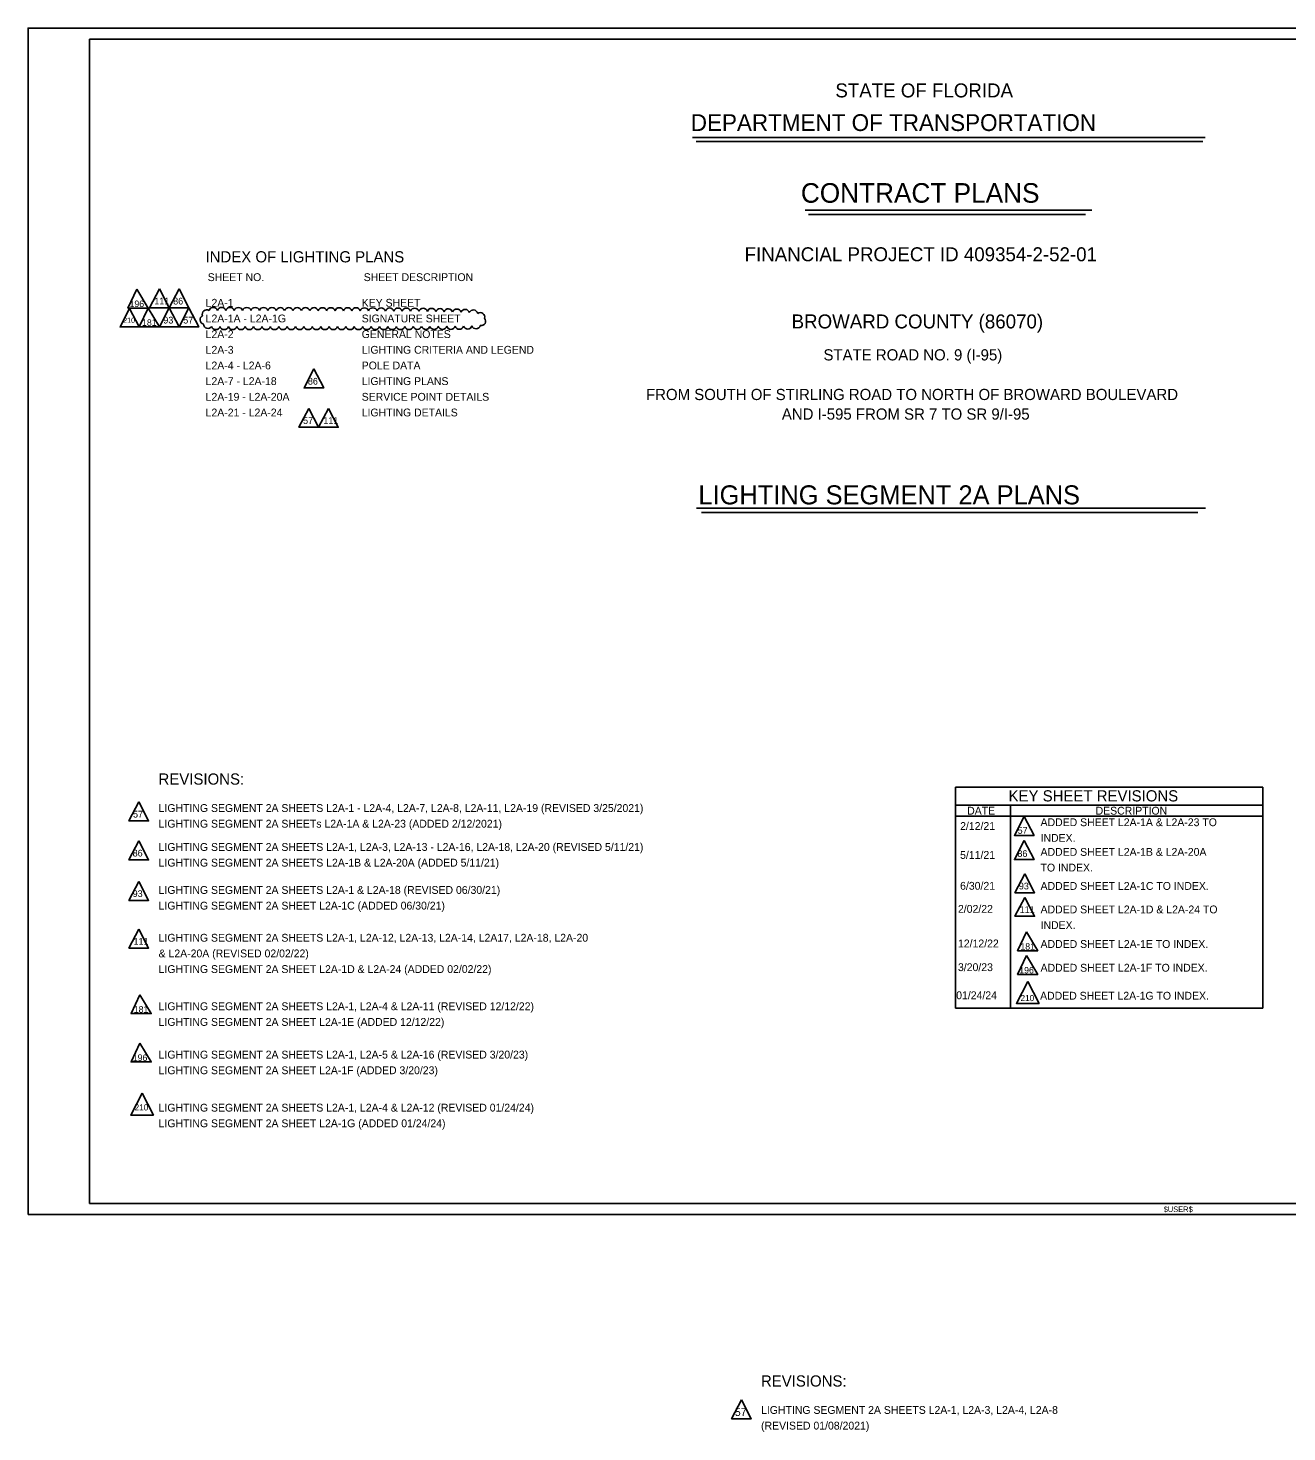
# Model space of a CAD drawing. Extents: x -820.2 to -798.7, y -2201.1 to -2188.5.
# Drawn here: x -820.23 to -808.98, y -2201.07 to -2188.52 of the extents above; entities that cross this region are included whole.
import ezdxf

# ---------------------------------------------------------------- set-up
doc = ezdxf.new("R2010")
doc.units = 0
for name, color, linetype in [('AdhocPoint_dp', 7, 'Continuous'), ('Cloud_dp', 7, 'Continuous'), ('PlotBorder_dp', 7, 'Continuous'), ('SheetBorder_dp', 7, 'Continuous'), ('SumBoxLines_dp', 7, 'Continuous'), ('TextLabel', 7, 'Continuous'), ('TextMinor', 7, 'Continuous'), ('TextNotes', 7, 'Continuous'), ('TextTitle', 7, 'Continuous')]:
    doc.layers.add(name, color=color, linetype=linetype)

msp = doc.modelspace()

# ---------------------------------------------------------------- linework, layer by layer
at = {"layer": 'AdhocPoint_dp'}
msp.add_line((-820.227, -2199.124), (-820.227, -2199.124), dxfattribs=at)
at = {"layer": 'Cloud_dp'}
for points in [[(-819.256, -2190.857), (-819.335, -2191.025), (-819.155, -2191.025)], [(-819.053, -2190.854), (-819.141, -2191.023), (-818.965, -2191.023)], [(-818.877, -2190.854), (-818.965, -2191.023), (-818.789, -2191.023)], [(-819.319, -2191.028), (-819.405, -2191.193), (-819.234, -2191.193)], [(-819.155, -2191.025), (-819.234, -2191.193), (-819.053, -2191.193)], [(-818.965, -2191.023), (-819.053, -2191.193), (-818.877, -2191.193)], [(-818.789, -2191.023), (-818.877, -2191.193), (-818.701, -2191.193)], [(-817.672, -2191.569), (-817.76, -2191.739), (-817.584, -2191.739)], [(-817.718, -2191.921), (-817.806, -2192.09), (-817.63, -2192.09)], [(-817.542, -2191.921), (-817.63, -2192.09), (-817.454, -2192.09)], [(-819.238, -2195.437), (-819.326, -2195.607), (-819.15, -2195.607)], [(-811.324, -2195.567), (-811.412, -2195.736), (-811.236, -2195.736)], [(-819.238, -2195.786), (-819.326, -2195.955), (-819.15, -2195.955)], [(-811.324, -2195.783), (-811.412, -2195.953), (-811.236, -2195.953)], [(-811.319, -2196.08), (-811.407, -2196.249), (-811.231, -2196.249)], [(-819.238, -2196.147), (-819.326, -2196.317), (-819.15, -2196.317)], [(-811.319, -2196.29), (-811.407, -2196.459), (-811.231, -2196.459)], [(-819.238, -2196.574), (-819.326, -2196.743), (-819.15, -2196.743)], [(-811.305, -2196.599), (-811.384, -2196.767), (-811.203, -2196.767)], [(-811.305, -2196.811), (-811.384, -2196.979), (-811.203, -2196.979)], [(-811.293, -2197.042), (-811.394, -2197.237), (-811.191, -2197.237)], [(-819.228, -2197.161), (-819.307, -2197.329), (-819.126, -2197.329)], [(-819.228, -2197.593), (-819.307, -2197.761), (-819.126, -2197.761)], [(-819.207, -2198.04), (-819.309, -2198.235), (-819.106, -2198.235)], [(-813.851, -2200.779), (-813.939, -2200.949), (-813.763, -2200.949)]]:
    msp.add_lwpolyline(points, close=True, dxfattribs=at)
for centre, radius, start, end in [((-818.631, -2191.079), 0.0393, 57.4429, 202.4429), ((-818.572, -2191.058), 0.0393, 17.4254, 162.4254), ((-818.497, -2191.058), 0.0393, 17.3487, 162.3487), ((-818.422, -2191.058), 0.0393, 17.3487, 162.3487), ((-818.347, -2191.059), 0.0393, 17.3487, 162.3487), ((-818.272, -2191.059), 0.0393, 17.3487, 162.3487), ((-818.197, -2191.059), 0.0393, 17.3487, 162.3487), ((-818.122, -2191.059), 0.0393, 17.3487, 162.3487), ((-818.047, -2191.059), 0.0393, 17.3487, 162.3487), ((-817.972, -2191.06), 0.0393, 17.3487, 162.3487), ((-817.897, -2191.06), 0.0393, 17.3487, 162.3487), ((-817.822, -2191.06), 0.0393, 17.3487, 162.3487), ((-817.747, -2191.06), 0.0393, 17.3487, 162.3487), ((-817.671, -2191.06), 0.0393, 17.3487, 162.3487), ((-817.596, -2191.061), 0.0393, 17.3487, 162.3487), ((-817.521, -2191.061), 0.0393, 17.3487, 162.3487), ((-817.446, -2191.061), 0.0393, 17.3487, 162.3487), ((-817.371, -2191.061), 0.0393, 17.3304, 162.3304), ((-817.296, -2191.061), 0.0393, 17.2888, 162.2888), ((-817.221, -2191.062), 0.0393, 17.2428, 162.2428), ((-817.146, -2191.062), 0.0393, 17.1914, 162.1914), ((-817.071, -2191.063), 0.0393, 17.1336, 162.1336), ((-816.996, -2191.063), 0.0393, 17.0679, 162.0679), ((-816.921, -2191.064), 0.0393, 16.9923, 161.9923), ((-816.846, -2191.064), 0.0393, 16.904, 161.904), ((-816.771, -2191.065), 0.0393, 16.799, 161.799), ((-816.696, -2191.066), 0.0393, 16.6713, 161.6713), ((-816.621, -2191.067), 0.0393, 16.5114, 161.5114), ((-816.546, -2191.069), 0.0393, 16.3028, 161.3028), ((-816.471, -2191.071), 0.0393, 16.0143, 161.0143), ((-816.396, -2191.073), 0.0393, 15.5766, 160.5766), ((-816.321, -2191.076), 0.0393, 14.7862, 159.7862), ((-816.247, -2191.081), 0.0394, 12.403, 157.403), ((-816.185, -2191.104), 0.0393, 341.3099, 126.3099), ((-818.651, -2191.13), 0.0393, 113.8298, 258.8298), ((-818.619, -2191.168), 0.0393, 180.98, 325.98), ((-818.549, -2191.178), 0.0393, 197.5, 342.5), ((-818.474, -2191.178), 0.0393, 197.5, 342.5), ((-818.399, -2191.178), 0.0393, 197.5, 342.5), ((-818.324, -2191.178), 0.0393, 197.5, 342.5), ((-818.249, -2191.178), 0.0393, 197.5, 342.5), ((-818.174, -2191.178), 0.0393, 197.5, 342.5), ((-818.099, -2191.178), 0.0393, 197.5, 342.5), ((-818.024, -2191.178), 0.0393, 197.5, 342.5), ((-817.949, -2191.178), 0.0393, 197.5, 342.5), ((-817.874, -2191.178), 0.0393, 197.5, 342.5), ((-817.799, -2191.178), 0.0393, 197.5, 342.5), ((-817.724, -2191.178), 0.0393, 197.5, 342.5), ((-817.649, -2191.178), 0.0393, 197.5, 342.5), ((-817.574, -2191.178), 0.0393, 197.5, 342.5), ((-817.499, -2191.178), 0.0393, 197.5, 342.5), ((-817.424, -2191.178), 0.0393, 197.5, 342.5), ((-817.349, -2191.178), 0.0393, 197.5052, 342.5052), ((-817.274, -2191.178), 0.0393, 197.5223, 342.5223), ((-817.199, -2191.178), 0.0393, 197.5417, 342.5417), ((-817.123, -2191.178), 0.0393, 197.5633, 342.5633), ((-817.048, -2191.178), 0.0393, 197.5876, 342.5876), ((-816.973, -2191.178), 0.0393, 197.6153, 342.6153), ((-816.898, -2191.178), 0.0393, 197.6471, 342.6471), ((-816.823, -2191.178), 0.0393, 197.6843, 342.6843), ((-816.748, -2191.177), 0.0393, 197.7285, 342.7285), ((-816.673, -2191.177), 0.0393, 197.7822, 342.7822), ((-816.598, -2191.177), 0.0393, 197.8496, 342.8496), ((-816.523, -2191.176), 0.0393, 197.9376, 342.9376), ((-816.448, -2191.176), 0.0393, 198.0595, 343.0595), ((-816.373, -2191.175), 0.0393, 198.2448, 343.2448), ((-816.298, -2191.173), 0.0393, 198.5811, 343.5811), ((-816.223, -2191.171), 0.0394, 199.6227, 344.6227), ((-816.177, -2191.143), 0.0393, 257.5478, 42.5478)]:
    msp.add_arc(centre, radius, start, end, dxfattribs=at)
at = {"layer": 'PlotBorder_dp'}
msp.add_lwpolyline([(-820.227, -2199.124), (-803.727, -2199.124), (-803.727, -2188.524), (-820.227, -2188.524)], close=True, dxfattribs=at)
at = {"layer": 'SheetBorder_dp'}
for p, q in [((-819.677, -2188.624), (-819.677, -2199.024)), ((-819.677, -2188.624), (-804.277, -2188.624)), ((-819.677, -2199.024), (-804.277, -2199.024))]:
    msp.add_line(p, q, dxfattribs=at)
at = {"layer": 'SumBoxLines_dp'}
for p, q in [((-811.938, -2195.306), (-811.938, -2197.281)), ((-811.938, -2195.306), (-809.191, -2195.306)), ((-809.191, -2195.306), (-809.191, -2197.281)), ((-811.938, -2195.466), (-809.191, -2195.466)), ((-811.938, -2195.566), (-809.191, -2195.566)), ((-811.448, -2195.466), (-811.448, -2197.281)), ((-811.938, -2197.281), (-809.191, -2197.281))]:
    msp.add_line(p, q, dxfattribs=at)
at = {"layer": 'TextTitle'}
for p, q in [((-814.289, -2189.5), (-809.707, -2189.5)), ((-814.257, -2189.538), (-809.729, -2189.538)), ((-813.281, -2190.15), (-810.719, -2190.15)), ((-813.253, -2190.188), (-810.777, -2190.188)), ((-814.252, -2192.813), (-809.704, -2192.813)), ((-814.209, -2192.851), (-809.772, -2192.851))]:
    msp.add_line(p, q, dxfattribs=at)

# ---------------------------------------------------------------- texts
at = {"layer": 'Cloud_dp'}
for s, height, p in [('111', 0.06, (-819.099, -2190.993)), ('86', 0.06, (-818.93, -2190.993)), ('93', 0.06, (-819.018, -2191.163)), ('57', 0.06, (-818.84, -2191.163)), ('86', 0.06, (-817.726, -2191.709)), ('57', 0.06, (-817.769, -2192.06)), ('111', 0.06, (-817.588, -2192.06)), ('57', 0.06, (-819.289, -2195.577)), ('57', 0.06, (-811.383, -2195.722)), ('86', 0.06, (-819.292, -2195.925)), ('86', 0.06, (-811.385, -2195.929)), ('93', 0.06, (-811.372, -2196.219)), ('93', 0.06, (-819.292, -2196.287)), ('111', 0.06, (-811.364, -2196.429)), ('111', 0.06, (-819.284, -2196.713)), ('57', 0.07, (-813.91, -2200.924))]:
    msp.add_text(s, height=height, rotation=0, dxfattribs=at).set_placement(p)
for s, height, p in [('196', 0.0582, (-819.32, -2191.016)), ('210', 0.0461, (-819.377, -2191.157)), ('181', 0.0582, (-819.208, -2191.184)), ('181', 0.0582, (-811.358, -2196.758)), ('196', 0.0582, (-811.368, -2196.97)), ('210', 0.0547, (-811.357, -2197.217)), ('181', 0.0582, (-819.282, -2197.32)), ('196', 0.0582, (-819.291, -2197.752)), ('210', 0.0547, (-819.275, -2198.194))]:
    msp.add_text(s, height=height, dxfattribs=at).set_placement(p)
at = {"layer": 'TextLabel'}
for s, height, p in [('INDEX OF LIGHTING PLANS', 0.1, (-818.641, -2190.617)), ('FINANCIAL PROJECT ID 409354-2-52-01', 0.125, (-813.823, -2190.607)), ('L2A-1', 0.07, (-818.64, -2191.013)), ('KEY SHEET', 0.07, (-817.245, -2191.013)), ('L2A-1A - L2A-1G', 0.07, (-818.64, -2191.153)), ('SIGNATURE SHEET', 0.07, (-817.245, -2191.153)), ('BROWARD COUNTY (86070)', 0.125, (-813.403, -2191.207)), ('L2A-2', 0.07, (-818.64, -2191.293)), ('GENERAL NOTES', 0.07, (-817.245, -2191.293)), ('L2A-3', 0.07, (-818.64, -2191.433)), ('LIGHTING CRITERIA AND LEGEND', 0.07, (-817.245, -2191.433)), ('STATE ROAD NO. 9 (I-95)', 0.1, (-813.118, -2191.493)), ('L2A-4 - L2A-6 ', 0.07, (-818.64, -2191.573)), ('POLE DATA', 0.07, (-817.245, -2191.573)), ('L2A-7 - L2A-18', 0.07, (-818.64, -2191.713)), ('LIGHTING PLANS', 0.07, (-817.245, -2191.713)), ('L2A-19 - L2A-20A', 0.07, (-818.64, -2191.853)), ('SERVICE POINT DETAILS', 0.07, (-817.245, -2191.853)), ('FROM SOUTH OF STIRLING ROAD TO NORTH OF BROWARD BOULEVARD', 0.1, (-814.704, -2191.847)), ('L2A-21 - L2A-24', 0.07, (-818.64, -2191.993)), ('LIGHTING DETAILS', 0.07, (-817.245, -2191.993)), ('AND I-595 FROM SR 7 TO SR 9/I-95', 0.1, (-813.49, -2192.022)), ('REVISIONS:', 0.1, (-819.061, -2195.283)), ('KEY SHEET REVISIONS', 0.1, (-811.464, -2195.433)), ('REVISIONS:', 0.1, (-813.677, -2200.661))]:
    msp.add_text(s, height=height, dxfattribs=at).set_placement(p)
at = {"layer": 'TextMinor'}
for s, height, p in [('ADDED SHEET L2A-1A & L2A-23 TO ', 0.07, (-811.178, -2195.654)), ('2/12/21', 0.07, (-811.897, -2195.688)), ('INDEX.', 0.07, (-811.178, -2195.794)), ('5/11/21', 0.07, (-811.897, -2195.946)), ('ADDED SHEET L2A-1B & L2A-20A ', 0.07, (-811.178, -2195.919)), ('TO INDEX.', 0.07, (-811.178, -2196.059)), ('6/30/21', 0.07, (-811.897, -2196.222)), ('ADDED SHEET L2A-1C TO INDEX.', 0.07, (-811.178, -2196.223)), ('2/02/22', 0.07, (-811.916, -2196.428)), ('ADDED SHEET L2A-1D & L2A-24 TO ', 0.07, (-811.178, -2196.433)), ('INDEX.', 0.07, (-811.178, -2196.573)), ('12/12/22', 0.07, (-811.916, -2196.737)), ('ADDED SHEET L2A-1E TO INDEX.', 0.07, (-811.178, -2196.742)), ('3/20/23', 0.07, (-811.916, -2196.949)), ('ADDED SHEET L2A-1F TO INDEX.', 0.07, (-811.178, -2196.954)), ('01/24/24', 0.07, (-811.932, -2197.2)), ('ADDED SHEET L2A-1G TO INDEX.', 0.07, (-811.182, -2197.204)), ('$USER$', 0.05, (-810.078, -2199.102))]:
    msp.add_text(s, height=height, dxfattribs=at).set_placement(p)
at = {"layer": 'TextNotes'}
for s, height, p in [('SHEET NO.', 0.07, (-818.621, -2190.784)), ('SHEET DESCRIPTION', 0.07, (-817.227, -2190.784)), ('LIGHTING SEGMENT 2A SHEETS L2A-1 - L2A-4, L2A-7, L2A-8, L2A-11, L2A-19 (REVISED 3/25/2021)', 0.06998, (-819.06, -2195.527)), ('DATE', 0.07, (-811.834, -2195.551)), ('DESCRIPTION', 0.07, (-810.686, -2195.551)), ('LIGHTING SEGMENT 2A SHEETs L2A-1A & L2A-23 (ADDED 2/12/2021)', 0.06998, (-819.06, -2195.667)), ('LIGHTING SEGMENT 2A SHEETS L2A-1, L2A-3, L2A-13 - L2A-16, L2A-18, L2A-20 (REVISED 5/11/21)', 0.06998, (-819.06, -2195.875)), ('LIGHTING SEGMENT 2A SHEETS L2A-1B & L2A-20A (ADDED 5/11/21)', 0.06998, (-819.06, -2196.015)), ('LIGHTING SEGMENT 2A SHEETS L2A-1 & L2A-18 (REVISED 06/30/21)', 0.06998, (-819.06, -2196.259)), ('LIGHTING SEGMENT 2A SHEET L2A-1C (ADDED 06/30/21)', 0.06998, (-819.06, -2196.399)), ('LIGHTING SEGMENT 2A SHEETS L2A-1, L2A-12, L2A-13, L2A-14, L2A17, L2A-18, L2A-20 ', 0.06998, (-819.06, -2196.686)), ('& L2A-20A (REVISED 02/02/22)', 0.06998, (-819.06, -2196.826)), ('LIGHTING SEGMENT 2A SHEET L2A-1D & L2A-24 (ADDED 02/02/22)', 0.06998, (-819.06, -2196.966)), ('LIGHTING SEGMENT 2A SHEETS L2A-1, L2A-4 & L2A-11 (REVISED 12/12/22)', 0.06998, (-819.06, -2197.298)), ('LIGHTING SEGMENT 2A SHEET L2A-1E (ADDED 12/12/22)', 0.06998, (-819.06, -2197.438)), ('LIGHTING SEGMENT 2A SHEETS L2A-1, L2A-5 & L2A-16 (REVISED 3/20/23)', 0.06998, (-819.06, -2197.73)), ('LIGHTING SEGMENT 2A SHEET L2A-1F (ADDED 3/20/23)', 0.06998, (-819.06, -2197.87)), ('LIGHTING SEGMENT 2A SHEETS L2A-1, L2A-4 & L2A-12 (REVISED 01/24/24)', 0.06998, (-819.06, -2198.204)), ('LIGHTING SEGMENT 2A SHEET L2A-1G (ADDED 01/24/24)', 0.06998, (-819.06, -2198.344)), ('LIGHTING SEGMENT 2A SHEETS L2A-1, L2A-3, L2A-4, L2A-8 ', 0.07, (-813.676, -2200.905)), ('(REVISED 01/08/2021)', 0.07, (-813.676, -2201.045))]:
    msp.add_text(s, height=height, dxfattribs=at).set_placement(p)
at = {"layer": 'TextTitle'}
for s, height, p in [('STATE OF FLORIDA', 0.125, (-813.012, -2189.143)), ('DEPARTMENT OF TRANSPORTATION', 0.15, (-814.304, -2189.443)), ('CONTRACT PLANS', 0.175, (-813.32, -2190.084)), ('LIGHTING SEGMENT 2A PLANS', 0.17, (-814.236, -2192.779))]:
    msp.add_text(s, height=height, dxfattribs=at).set_placement(p)

doc.saveas('drawing.dxf')
